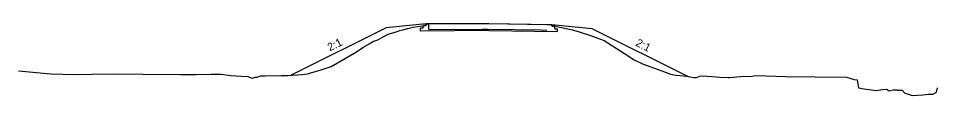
# Model space of a CAD drawing. Extents: x -41 to 232, y -116 to 22.
# Drawn here: x 70.8 to 231.5, y -64.9 to -52.2 of the extents above; entities that cross this region are included whole.
import ezdxf

# ---------------------------------------------------------------- set-up
doc = ezdxf.new("R2010")
doc.units = 0
for name, color, linetype in [('RD_X_Concrete_Pad', 7, 'Continuous'), ('RD_X_GR_Rt', 7, 'Continuous'), ('SV_X_Break_Lines', 7, 'Continuous'), ('UT_X_Telecom', 7, 'Continuous'), ('VG_X_Cells', 7, 'Continuous')]:
    doc.layers.add(name, color=color, linetype=linetype)

msp = doc.modelspace()

# ---------------------------------------------------------------- linework, layer by layer
at = {"layer": 'RD_X_Concrete_Pad'}
msp.add_lwpolyline([(70.76, -60.5), (76.41, -61.06), (80.49, -61.15), (83.66, -61.09), (88.35, -61.07), (92.5, -61.11), (99.14, -61.15), (101.86, -61.18), (104.45, -61.13), (106.17, -61.12), (107.95, -61.33), (109.7, -61.49), (110.89, -61.51), (111.12, -61.63), (111.49, -61.77), (111.74, -61.79), (112.17, -61.64), (112.54, -61.64), (113.11, -61.42), (113.94, -61.43), (116.7, -61.35), (117.88, -61.34), (120.41, -61.17), (121.33, -61.05), (122.48, -60.7), (123.72, -60.38), (125.44, -59.75), (129.9, -57.2), (131.01, -56.45), (132.32, -55.66), (132.76, -55.4), (133.61, -55.06), (135.45, -54.1), (136.82, -53.68), (137.47, -53.45), (138.21, -53.28), (138.87, -53.07), (139.8, -52.87), (140.56, -52.74), (141.45, -52.65), (141.96, -52.59), (142.11, -52.45), (142.14, -52.4), (142.17, -52.36), (142.23, -52.34), (142.52, -52.29), (151.8, -52.21), (153.06, -52.2), (163.18, -52.37), (163.99, -52.47), (164.04, -52.54), (164.09, -52.66), (164.9, -52.77), (165.47, -52.88), (166.84, -53.15), (167.67, -53.31), (168.84, -53.67), (170.83, -54.3), (171.9, -54.72), (173.21, -55.2), (176.77, -57.48), (178.43, -58.58), (179.9, -59.29), (183.28, -60.55), (184.78, -61.09), (185.81, -61.3), (186.5, -61.37), (187.62, -61.45), (188.9, -61.71), (189.32, -61.7), (189.94, -61.46), (190.44, -61.4), (192.76, -61.56), (193.41, -61.62), (194.91, -61.71), (195.11, -61.7), (197.06, -61.52), (199.01, -61.44), (199.7, -61.37), (204.94, -61.55), (210.1, -61.61), (215.56, -61.64), (216.9, -62.03), (217.46, -62.1), (217.66, -63.51), (218.65, -63.7), (220.77, -63.96), (221.88, -63.79), (222.55, -63.73), (222.88, -63.94), (223.04, -64.02), (223.76, -63.87), (224.4, -63.89), (224.49, -63.92), (225.32, -63.91), (225.79, -64.46), (226.18, -64.59), (227.05, -64.88), (228.92, -64.72), (229.88, -64.65), (230.7, -64.62), (231.31, -64.29), (231.51, -63.52)], dxfattribs=at)
at = {"layer": 'RD_X_GR_Rt'}
for p, q in [((135.06, -53), (118.45, -61.3)), ((142.06, -52.3), (135.06, -53)), ((164.06, -52.38), (171.06, -53.08)), ((171.06, -53.08), (187.9, -61.51))]:
    msp.add_line(p, q, dxfattribs=at)
at = {"layer": 'UT_X_Telecom'}
msp.add_line((142.52, -53.29), (142.52, -52.29), dxfattribs=at)
msp.add_lwpolyline([(142.52, -53.29), (151.8, -53.21), (152.92, -53.2), (162.17, -53.35), (163.18, -53.37)], dxfattribs=at)
at = {"layer": 'VG_X_Cells'}
for p, q in [((142.06, -52.55), (141.56, -52.55)), ((141.56, -53.05), (141.56, -52.55)), ((153.06, -52.2), (142.06, -52.3)), ((142.06, -52.55), (142.06, -52.3)), ((153.06, -52.2), (164.06, -52.38)), ((164.06, -52.63), (164.06, -52.38)), ((164.06, -52.63), (164.56, -52.64)), ((164.56, -53.14), (164.56, -52.64)), ((141.56, -53.05), (141.06, -53.06)), ((141.06, -53.56), (141.06, -53.06)), ((153.06, -53.45), (141.06, -53.56)), ((153.06, -53.45), (165.06, -53.65)), ((164.56, -53.14), (165.06, -53.15)), ((165.06, -53.65), (165.06, -53.15))]:
    msp.add_line(p, q, dxfattribs=at)

# ---------------------------------------------------------------- texts
at = {"layer": 'SV_X_Break_Lines'}
for rotation, p in [(26.5651, (125.23, -57.13)), (333.4349, (178.58, -56.06))]:
    msp.add_text('2:1', height=1.4, rotation=rotation, dxfattribs=at).set_placement(p)

doc.saveas('drawing.dxf')
